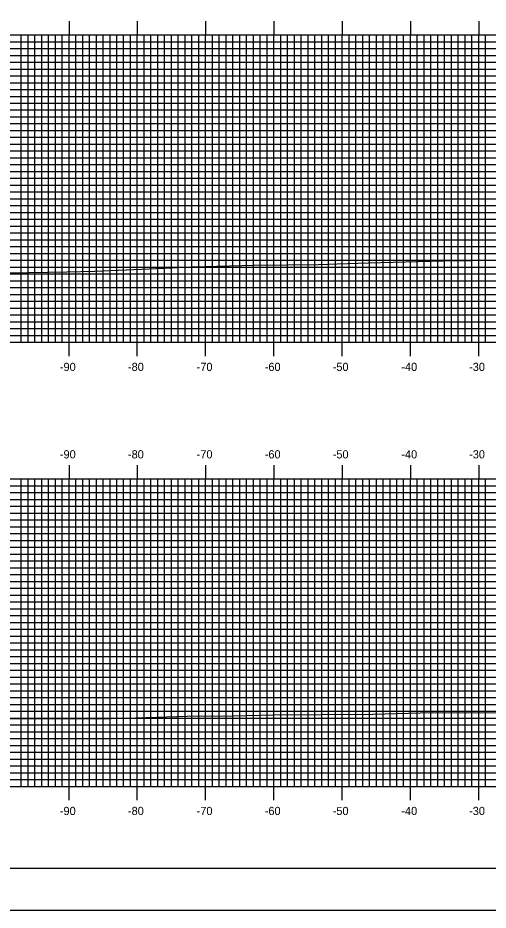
# Model space of a CAD drawing. Extents: x 485 to 829, y -1658 to -1438.
# Drawn here: x 553.6 to 622.5, y -1657.7 to -1527.1 of the extents above; entities that cross this region are included whole.
import ezdxf

# ---------------------------------------------------------------- set-up
doc = ezdxf.new("R2010")
doc.units = 0
for name, color, linetype in [('BORDER', 7, 'Continuous'), ('H_V ANNOTATION', 7, 'Continuous'), ('MAJOR', 7, 'Continuous'), ('MINOR', 7, 'Continuous'), ('PLOT BOUNDARY', 7, 'Continuous'), ('S_Roadway_Centerline', 7, 'Continuous')]:
    doc.layers.add(name, color=color, linetype=linetype)

msp = doc.modelspace()

# ---------------------------------------------------------------- linework, layer by layer
at = {"layer": 'BORDER'}
msp.add_lwpolyline([(501.53, -1651.6), (821.53, -1651.6), (821.53, -1441.6), (501.53, -1441.6)], close=True, dxfattribs=at)
at = {"layer": 'MAJOR'}
for p, q in [((561.13, -1527.6), (561.13, -1529.6)), ((571.13, -1527.6), (571.13, -1529.6)), ((581.13, -1527.6), (581.13, -1529.6)), ((591.13, -1527.6), (591.13, -1529.6)), ((601.13, -1527.6), (601.13, -1529.6)), ((611.13, -1527.6), (611.13, -1529.6)), ((621.13, -1527.6), (621.13, -1529.6)), ((511.13, -1529.6), (791.13, -1529.6)), ((511.13, -1529.6), (791.13, -1529.6)), ((561.13, -1574.6), (561.13, -1529.6)), ((571.13, -1574.6), (571.13, -1529.6)), ((581.13, -1574.6), (581.13, -1529.6)), ((591.13, -1574.6), (591.13, -1529.6)), ((601.13, -1574.6), (601.13, -1529.6)), ((611.13, -1574.6), (611.13, -1529.6)), ((621.13, -1574.6), (621.13, -1529.6)), ((511.13, -1534.6), (791.13, -1534.6)), ((511.13, -1539.6), (791.13, -1539.6)), ((511.13, -1544.6), (791.13, -1544.6)), ((511.13, -1549.6), (791.13, -1549.6)), ((511.13, -1554.6), (791.13, -1554.6)), ((511.13, -1559.6), (791.13, -1559.6)), ((511.13, -1564.6), (791.13, -1564.6)), ((511.13, -1569.6), (791.13, -1569.6)), ((511.13, -1574.6), (791.13, -1574.6)), ((511.13, -1574.6), (791.13, -1574.6)), ((561.13, -1576.61), (561.13, -1574.6)), ((571.13, -1576.61), (571.13, -1574.6)), ((581.13, -1576.61), (581.13, -1574.6)), ((591.13, -1576.61), (591.13, -1574.6)), ((601.13, -1576.61), (601.13, -1574.6)), ((611.13, -1576.61), (611.13, -1574.6)), ((621.13, -1576.61), (621.13, -1574.6)), ((561.13, -1592.6), (561.13, -1594.6)), ((571.13, -1592.6), (571.13, -1594.6)), ((581.13, -1592.6), (581.13, -1594.6)), ((591.13, -1592.6), (591.13, -1594.6)), ((601.13, -1592.6), (601.13, -1594.6)), ((611.13, -1592.6), (611.13, -1594.6)), ((621.13, -1592.6), (621.13, -1594.6)), ((511.13, -1594.6), (791.13, -1594.6)), ((511.13, -1594.6), (791.13, -1594.6)), ((561.13, -1639.6), (561.13, -1594.6)), ((571.13, -1639.6), (571.13, -1594.6)), ((581.13, -1639.6), (581.13, -1594.6)), ((591.13, -1639.6), (591.13, -1594.6)), ((601.13, -1639.6), (601.13, -1594.6)), ((611.13, -1639.6), (611.13, -1594.6)), ((621.13, -1639.6), (621.13, -1594.6)), ((511.13, -1599.6), (791.13, -1599.6)), ((511.13, -1604.6), (791.13, -1604.6)), ((511.13, -1609.6), (791.13, -1609.6)), ((511.13, -1614.6), (791.13, -1614.6)), ((511.13, -1619.6), (791.13, -1619.6)), ((511.13, -1624.6), (791.13, -1624.6)), ((511.13, -1629.6), (791.13, -1629.6)), ((511.13, -1634.6), (791.13, -1634.6)), ((511.13, -1639.6), (791.13, -1639.6)), ((511.13, -1639.6), (791.13, -1639.6)), ((561.13, -1641.61), (561.13, -1639.6)), ((571.13, -1641.61), (571.13, -1639.6)), ((581.13, -1641.61), (581.13, -1639.6)), ((591.13, -1641.61), (591.13, -1639.6)), ((601.13, -1641.61), (601.13, -1639.6)), ((611.13, -1641.61), (611.13, -1639.6)), ((621.13, -1641.61), (621.13, -1639.6))]:
    msp.add_line(p, q, dxfattribs=at)
at = {"layer": 'MINOR'}
for p, q in [((511.13, -1530.6), (791.13, -1530.6)), ((554.13, -1574.6), (554.13, -1529.6)), ((555.13, -1574.6), (555.13, -1529.6)), ((556.13, -1574.6), (556.13, -1529.6)), ((557.13, -1574.6), (557.13, -1529.6)), ((558.13, -1574.6), (558.13, -1529.6)), ((559.13, -1574.6), (559.13, -1529.6)), ((560.13, -1574.6), (560.13, -1529.6)), ((562.13, -1574.6), (562.13, -1529.6)), ((563.13, -1574.6), (563.13, -1529.6)), ((564.13, -1574.6), (564.13, -1529.6)), ((565.13, -1574.6), (565.13, -1529.6)), ((566.13, -1574.6), (566.13, -1529.6)), ((567.13, -1574.6), (567.13, -1529.6)), ((568.13, -1574.6), (568.13, -1529.6)), ((569.13, -1574.6), (569.13, -1529.6)), ((570.13, -1574.6), (570.13, -1529.6)), ((572.13, -1574.6), (572.13, -1529.6)), ((573.13, -1574.6), (573.13, -1529.6)), ((574.13, -1574.6), (574.13, -1529.6)), ((575.13, -1574.6), (575.13, -1529.6)), ((576.13, -1574.6), (576.13, -1529.6)), ((577.13, -1574.6), (577.13, -1529.6)), ((578.13, -1574.6), (578.13, -1529.6)), ((579.13, -1574.6), (579.13, -1529.6)), ((580.13, -1574.6), (580.13, -1529.6)), ((582.13, -1574.6), (582.13, -1529.6)), ((583.13, -1574.6), (583.13, -1529.6)), ((584.13, -1574.6), (584.13, -1529.6)), ((585.13, -1574.6), (585.13, -1529.6)), ((586.13, -1574.6), (586.13, -1529.6)), ((587.13, -1574.6), (587.13, -1529.6)), ((588.13, -1574.6), (588.13, -1529.6)), ((589.13, -1574.6), (589.13, -1529.6)), ((590.13, -1574.6), (590.13, -1529.6)), ((592.13, -1574.6), (592.13, -1529.6)), ((593.13, -1574.6), (593.13, -1529.6)), ((594.13, -1574.6), (594.13, -1529.6)), ((595.13, -1574.6), (595.13, -1529.6)), ((596.13, -1574.6), (596.13, -1529.6)), ((597.13, -1574.6), (597.13, -1529.6)), ((598.13, -1574.6), (598.13, -1529.6)), ((599.13, -1574.6), (599.13, -1529.6)), ((600.13, -1574.6), (600.13, -1529.6)), ((602.13, -1574.6), (602.13, -1529.6)), ((603.13, -1574.6), (603.13, -1529.6)), ((604.13, -1574.6), (604.13, -1529.6)), ((605.13, -1574.6), (605.13, -1529.6)), ((606.13, -1574.6), (606.13, -1529.6)), ((607.13, -1574.6), (607.13, -1529.6)), ((608.13, -1574.6), (608.13, -1529.6)), ((609.13, -1574.6), (609.13, -1529.6)), ((610.13, -1574.6), (610.13, -1529.6)), ((612.13, -1574.6), (612.13, -1529.6)), ((613.13, -1574.6), (613.13, -1529.6)), ((614.13, -1574.6), (614.13, -1529.6)), ((615.13, -1574.6), (615.13, -1529.6)), ((616.13, -1574.6), (616.13, -1529.6)), ((617.13, -1574.6), (617.13, -1529.6)), ((618.13, -1574.6), (618.13, -1529.6)), ((619.13, -1574.6), (619.13, -1529.6)), ((620.13, -1574.6), (620.13, -1529.6)), ((622.13, -1574.6), (622.13, -1529.6)), ((511.13, -1531.6), (791.13, -1531.6)), ((511.13, -1532.6), (791.13, -1532.6)), ((511.13, -1533.6), (791.13, -1533.6)), ((511.13, -1535.6), (791.13, -1535.6)), ((511.13, -1536.6), (791.13, -1536.6)), ((511.13, -1537.6), (791.13, -1537.6)), ((511.13, -1538.6), (791.13, -1538.6)), ((511.13, -1540.6), (791.13, -1540.6)), ((511.13, -1541.6), (791.13, -1541.6)), ((511.13, -1542.6), (791.13, -1542.6)), ((511.13, -1543.6), (791.13, -1543.6)), ((511.13, -1545.6), (791.13, -1545.6)), ((511.13, -1546.6), (791.13, -1546.6)), ((511.13, -1547.6), (791.13, -1547.6)), ((511.13, -1548.6), (791.13, -1548.6)), ((511.13, -1550.6), (791.13, -1550.6)), ((511.13, -1551.6), (791.13, -1551.6)), ((511.13, -1552.6), (791.13, -1552.6)), ((511.13, -1553.6), (791.13, -1553.6)), ((511.13, -1555.6), (791.13, -1555.6)), ((511.13, -1556.6), (791.13, -1556.6)), ((511.13, -1557.6), (791.13, -1557.6)), ((511.13, -1558.6), (791.13, -1558.6)), ((511.13, -1560.6), (791.13, -1560.6)), ((511.13, -1561.6), (791.13, -1561.6)), ((511.13, -1562.6), (791.13, -1562.6)), ((511.13, -1563.6), (791.13, -1563.6)), ((511.13, -1565.6), (791.13, -1565.6)), ((511.13, -1566.6), (791.13, -1566.6)), ((511.13, -1567.6), (791.13, -1567.6)), ((511.13, -1568.6), (791.13, -1568.6)), ((511.13, -1570.6), (791.13, -1570.6)), ((511.13, -1571.6), (791.13, -1571.6)), ((511.13, -1572.6), (791.13, -1572.6)), ((511.13, -1573.6), (791.13, -1573.6)), ((554.13, -1639.6), (554.13, -1594.6)), ((555.13, -1639.6), (555.13, -1594.6)), ((556.13, -1639.6), (556.13, -1594.6)), ((557.13, -1639.6), (557.13, -1594.6)), ((558.13, -1639.6), (558.13, -1594.6)), ((559.13, -1639.6), (559.13, -1594.6)), ((560.13, -1639.6), (560.13, -1594.6)), ((562.13, -1639.6), (562.13, -1594.6)), ((563.13, -1639.6), (563.13, -1594.6)), ((564.13, -1639.6), (564.13, -1594.6)), ((565.13, -1639.6), (565.13, -1594.6)), ((566.13, -1639.6), (566.13, -1594.6)), ((567.13, -1639.6), (567.13, -1594.6)), ((568.13, -1639.6), (568.13, -1594.6)), ((569.13, -1639.6), (569.13, -1594.6)), ((570.13, -1639.6), (570.13, -1594.6)), ((572.13, -1639.6), (572.13, -1594.6)), ((573.13, -1639.6), (573.13, -1594.6)), ((574.13, -1639.6), (574.13, -1594.6)), ((575.13, -1639.6), (575.13, -1594.6)), ((576.13, -1639.6), (576.13, -1594.6)), ((577.13, -1639.6), (577.13, -1594.6)), ((578.13, -1639.6), (578.13, -1594.6)), ((579.13, -1639.6), (579.13, -1594.6)), ((580.13, -1639.6), (580.13, -1594.6)), ((582.13, -1639.6), (582.13, -1594.6)), ((583.13, -1639.6), (583.13, -1594.6)), ((584.13, -1639.6), (584.13, -1594.6)), ((585.13, -1639.6), (585.13, -1594.6)), ((586.13, -1639.6), (586.13, -1594.6)), ((587.13, -1639.6), (587.13, -1594.6)), ((588.13, -1639.6), (588.13, -1594.6)), ((589.13, -1639.6), (589.13, -1594.6)), ((590.13, -1639.6), (590.13, -1594.6)), ((592.13, -1639.6), (592.13, -1594.6)), ((593.13, -1639.6), (593.13, -1594.6)), ((594.13, -1639.6), (594.13, -1594.6)), ((595.13, -1639.6), (595.13, -1594.6)), ((596.13, -1639.6), (596.13, -1594.6)), ((597.13, -1639.6), (597.13, -1594.6)), ((598.13, -1639.6), (598.13, -1594.6)), ((599.13, -1639.6), (599.13, -1594.6)), ((600.13, -1639.6), (600.13, -1594.6)), ((602.13, -1639.6), (602.13, -1594.6)), ((603.13, -1639.6), (603.13, -1594.6)), ((604.13, -1639.6), (604.13, -1594.6)), ((605.13, -1639.6), (605.13, -1594.6)), ((606.13, -1639.6), (606.13, -1594.6)), ((607.13, -1639.6), (607.13, -1594.6)), ((608.13, -1639.6), (608.13, -1594.6)), ((609.13, -1639.6), (609.13, -1594.6)), ((610.13, -1639.6), (610.13, -1594.6)), ((612.13, -1639.6), (612.13, -1594.6)), ((613.13, -1639.6), (613.13, -1594.6)), ((614.13, -1639.6), (614.13, -1594.6)), ((615.13, -1639.6), (615.13, -1594.6)), ((616.13, -1639.6), (616.13, -1594.6)), ((617.13, -1639.6), (617.13, -1594.6)), ((618.13, -1639.6), (618.13, -1594.6)), ((619.13, -1639.6), (619.13, -1594.6)), ((620.13, -1639.6), (620.13, -1594.6)), ((622.13, -1639.6), (622.13, -1594.6)), ((511.13, -1595.6), (791.13, -1595.6)), ((511.13, -1596.6), (791.13, -1596.6)), ((511.13, -1597.6), (791.13, -1597.6)), ((511.13, -1598.6), (791.13, -1598.6)), ((511.13, -1600.6), (791.13, -1600.6)), ((511.13, -1601.6), (791.13, -1601.6)), ((511.13, -1602.6), (791.13, -1602.6)), ((511.13, -1603.6), (791.13, -1603.6)), ((511.13, -1605.6), (791.13, -1605.6)), ((511.13, -1606.6), (791.13, -1606.6)), ((511.13, -1607.6), (791.13, -1607.6)), ((511.13, -1608.6), (791.13, -1608.6)), ((511.13, -1610.6), (791.13, -1610.6)), ((511.13, -1611.6), (791.13, -1611.6)), ((511.13, -1612.6), (791.13, -1612.6)), ((511.13, -1613.6), (791.13, -1613.6)), ((511.13, -1615.6), (791.13, -1615.6)), ((511.13, -1616.6), (791.13, -1616.6)), ((511.13, -1617.6), (791.13, -1617.6)), ((511.13, -1618.6), (791.13, -1618.6)), ((511.13, -1620.6), (791.13, -1620.6)), ((511.13, -1621.6), (791.13, -1621.6)), ((511.13, -1622.6), (791.13, -1622.6)), ((511.13, -1623.6), (791.13, -1623.6)), ((511.13, -1625.6), (791.13, -1625.6)), ((511.13, -1626.6), (791.13, -1626.6)), ((511.13, -1627.6), (791.13, -1627.6)), ((511.13, -1628.6), (791.13, -1628.6)), ((511.13, -1630.6), (791.13, -1630.6)), ((511.13, -1631.6), (791.13, -1631.6)), ((511.13, -1632.6), (791.13, -1632.6)), ((511.13, -1633.6), (791.13, -1633.6)), ((511.13, -1635.6), (791.13, -1635.6)), ((511.13, -1636.6), (791.13, -1636.6)), ((511.13, -1637.6), (791.13, -1637.6)), ((511.13, -1638.6), (791.13, -1638.6))]:
    msp.add_line(p, q, dxfattribs=at)
at = {"layer": 'PLOT BOUNDARY'}
msp.add_lwpolyline([(485.35, -1657.72), (825.35, -1657.72), (825.35, -1437.72), (485.35, -1437.72)], close=True, dxfattribs=at)
at = {"layer": 'S_Roadway_Centerline'}
for points in [[(511.13, -1565.67), (522.61, -1565.21), (527.92, -1564.98), (537.05, -1564.77), (540, -1564.68), (541.68, -1564.68), (552.34, -1564.43), (560.82, -1564.28), (564.84, -1564.2), (571.8, -1563.91), (579.14, -1563.58), (588.25, -1563.29), (597.66, -1563.2), (600.37, -1563.13), (604.91, -1562.98), (615.91, -1562.69), (624.29, -1562.57)], [(511.13, -1630.76), (515.97, -1630.68), (524.55, -1630.38), (542.88, -1629.72), (544.02, -1629.69), (544.86, -1629.7), (550.35, -1629.68), (565.48, -1629.71), (570.93, -1629.57), (578.45, -1629.33), (585.05, -1629.28), (590.98, -1629.12), (598.18, -1629.1), (605.63, -1629.02), (614.3, -1628.78), (626.36, -1628.86)]]:
    msp.add_lwpolyline(points, dxfattribs=at)

# ---------------------------------------------------------------- texts
at = {"layer": 'H_V ANNOTATION'}
for s, p in [('-90', (559.79, -1578.8)), ('-80', (569.76, -1578.8)), ('-70', (579.82, -1578.8)), ('-60', (589.79, -1578.8)), ('-50', (599.74, -1578.8)), ('-40', (609.79, -1578.8)), ('-30', (619.71, -1578.8)), ('-90', (559.79, -1591.6)), ('-80', (569.76, -1591.6)), ('-70', (579.82, -1591.6)), ('-60', (589.79, -1591.6)), ('-50', (599.74, -1591.6)), ('-40', (609.79, -1591.6)), ('-30', (619.71, -1591.6)), ('-90', (559.79, -1643.8)), ('-80', (569.76, -1643.8)), ('-70', (579.82, -1643.8)), ('-60', (589.79, -1643.8)), ('-50', (599.74, -1643.8)), ('-40', (609.79, -1643.8)), ('-30', (619.71, -1643.8))]:
    msp.add_text(s, height=1.2, dxfattribs=at).set_placement(p)

doc.saveas('drawing.dxf')
